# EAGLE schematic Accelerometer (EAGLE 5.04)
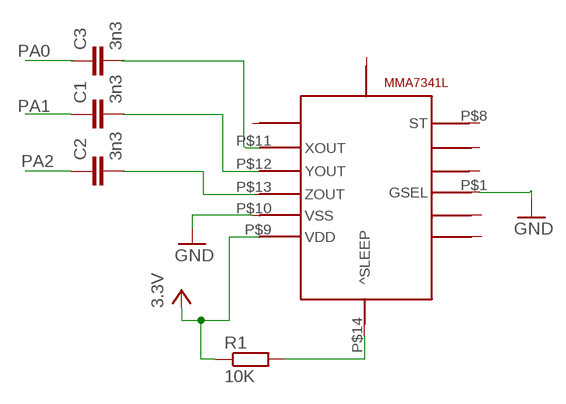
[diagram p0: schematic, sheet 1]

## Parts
C1  3n3  C2,5-3  [C2.5-3]
C2  3n3  C2,5-3  [C2.5-3]
C3  3n3  C2,5-3  [C2.5-3]
R1  10K  R-EU_0204/2V  [0204V]
U$1  MMA7341L  [MMA7341L]

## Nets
GND: U$1.P$1(GSEL)
N$1: U$1.P$14(^SLEEP)
N$2: U$1.P$10(VSS)
PA1: C1.1
PA2: C2.1
VCC: R1.1 ; supply symbol labelled 3.3V
Unconnected: C1.2 C2.2 C3.1 C3.2 R1.2 U$1.P$2(N/C) U$1.P$3 U$1.P$4 U$1.P$5 U$1.P$6 U$1.P$7 U$1.P$8(ST) U$1.P$9(VDD) U$1.P$11(XOUT) U$1.P$12(YOUT) U$1.P$13(ZOUT)

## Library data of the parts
C1-C3 = capacitor-wima:C: CAPACITOR
R1 = resistor:R-EU_: RESISTOR, European symbol
U$1 = MMA7341L:MMA7341L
